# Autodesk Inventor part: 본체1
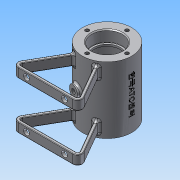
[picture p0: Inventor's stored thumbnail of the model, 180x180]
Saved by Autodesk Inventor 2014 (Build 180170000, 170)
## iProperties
Created: 2016-03
Part Number: 본체1
Material: 알루미늄 6061
Document SubType Name: Modeling
Designer: NET
Density: 2.71 g/cm^3
Appearance: 알루미늄 - 평지
Mass: 209.662 g
Surface Area: 328.168 cm^2
Volume: 77.3661 cm^3
Author: NET
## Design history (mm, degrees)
sketch "스케치1"
  geometry: C1 r 26 at (0, 0); 1 further point
  constraints: 1 centre point, 1 coincident
  dimensions: "d0" = 52 diameter of C1
extrude "돌출1" new body sketch "스케치1" stored distance "d1" = 70; taper "d2" = 0 deg
node "작업 평면2"
sketch "스케치2"
  geometry: 1 further point
sketch "스케치3"
  geometry: L1 (0, 0)-(0, -65); L2 (0, 0)-(58.644, 0); L3 (0, -65)-(-37.528, -65); L4 (-37.528, -65)-(37.528, -65); L5 (-32.332, -62)-(32.332, -62); L6 (11.547, -20)-(37.528, -65); L7 (-9.815, -23)-(-32.332, -62); L8 (32.332, -62)-(9.815, -23); L9 (-11.547, -20)-(-37.528, -65); L10 (-11.547, -20)-(11.547, -20); L11 (9.815, -23)-(-9.815, -23); C1 r 26 at (0, 0) reference; 2 further points
  constraints: 22 end point, 2 midpoint, 2 parallel, 1 horizontal, 1 point on line, 1 vertical
  dimensions: "d4" = 65 distance of L1.end L1.start; "d10" = 3 distance between parallel lines of L4 L5; "d13" = 3 distance between parallel lines of L11 L10; "d14" = 3 distance between parallel lines of L6 L8; "d15" = 3 distance between parallel lines of L9 L7; "d17" = 51.96152 distance of L6.start L4.end; "d18" = 60 deg angle of L8 L7; "d19" = 75.05553 distance of L3.end L4.end; "d112" = 45 distance between parallel lines of L4 L10
extrude "돌출2" join sketch "스케치3" distance "d20" = 10; taper "d21" = 0 deg
fillet "모깎기1" dims "d22" = 5
fillet "모깎기2" dims "d23" = 2
sketch "스케치4"
  geometry: C1 r 26 at (0, 0) reference; C2 r 16 at (0, 0)
  constraints: 1 centre point, 1 coincident
  dimensions: "d24" = 32 diameter of C2
extrude "돌출3" cut sketch "스케치4" distance "d25" = 12; taper "d26" = 0 deg
sketch "스케치5"
  geometry: C1 r 16 at (0, 0) reference; C2 r 14 at (0, 0)
  constraints: 1 centre point, 1 coincident
  dimensions: "d27" = 28 diameter of C2
extrude "돌출4" cut sketch "스케치5" distance "d28" = 2; taper "d29" = 0 deg
node "작업 평면4"
fillet "모깎기3" dims "d33" = 0.3
node "작업 평면5"
sketch "스케치7"
  geometry: C1 r 21 at (0, 0); 1 further point
  constraints: 1 centre point, 1 coincident
  dimensions: "d37" = 42 diameter of C1
extrude "돌출6" cut sketch "스케치7" stored distance "d38" = 42; taper "d39" = 0 deg
fillet "모깎기7" dims "d40" = 3
fillet "모깎기8" dims "d41" = 0.3
node "작업 평면6"
sketch "스케치8"
  geometry: C1 r 5 at (0, 0); 1 further point
  constraints: 1 centre point, 1 coincident
  dimensions: "d43" = 10 diameter of C1
extrude "돌출7" join sketch "스케치8" stored distance "d44" = 42; taper "d45" = 0 deg
sketch "스케치9"
  geometry: L1 (0, 0)-(7.506, -28.012); L2 (0, 0)-(0, -26); 2 further points
  constraints: 4 end point, 1 coincident, 1 vertical, 1 vertical alignment, 1 other
  dimensions: "d46" = 15 deg angle of L1 L2; "d47" = 29 distance of L1.start L1.end
node "작업 평면7"
sketch "스케치10"
  geometry: C1 r 6 at (0, 0); 1 further point
  constraints: 1 centre point, 1 coincident
  dimensions: "d48" = 12 diameter of C1
extrude "돌출8" join sketch "스케치10" stored distance "d49" = 42; taper "d50" = 0 deg
hole "구멍1" diameter "d53" = 5.188; stored, may be unused: countersink angle "d57" = 90 deg, drill point angle "d59" = 118 deg; dims "d51" = 10, "d52" = 10, "d54" = 10, "d55" = 4, "d56" = 2, "d58" = 10
hole "구멍2" diameter "d62" = 5.188; stored, may be unused: countersink angle "d66" = 90 deg, drill point angle "d68" = 118 deg; dims "d60" = 10, "d61" = 10, "d63" = 10, "d64" = 4, "d65" = 2, "d67" = 10
fillet "모깎기9" dims "d69" = 2
fillet "모깎기10" dims "d70" = 2
fillet "모깎기11" dims "d71" = 2
fillet "모깎기12" dims "d72" = 5
sketch "스케치11"
  geometry: L1 (0, 0)-(57.735, 0) reference; L2 (57.735, 10)-(0, 10) reference; L3 (28.868, 10)-(28.868, 0); C1 r 3 at (8.868, 5); C2 r 3 at (48.868, 5); 1 further point
  constraints: 2 centre point, 2 end point, 2 midpoint, 1 horizontal alignment
  dimensions: "d73" = 6 diameter of C1; "d74" = 6 diameter of C2; "d75" = 20 distance from line of C1.centre L3; "d76" = 40 distance of C2.centre C1.centre; "d77" = 5 distance from line of L1 C1.centre
extrude "돌출9" cut sketch "스케치11" distance "d78" = 42; taper "d79" = 0 deg
node "작업 평면8"
sketch "스케치12"
  geometry: L1 (26, 35)-(-26, 35) reference; 2 further points
  constraints: 1 coincident, 1 other
feature "엠보싱1" sketch "스케치12" dims "d20" = 10, "d21" = 0, "d82" = 0.5, "d83" = 0
chamfer "모따기1" distance "d84" = 1; stored, may be unused: second distance "d85" = 2, angle "d86" = 45 deg
chamfer "모따기2" distance "d87" = 1; stored, may be unused: second distance "d88" = 2, angle "d89" = 45 deg
sketch "스케치13" dims "d91" = 42
  geometry: L1 (0, 21)-(0, 0); C1 r 17 at (0, 0) reference; 1 further point
  constraints: 2 coincident, 2 end point, 1 vertical, 1 vertical alignment, 2 other
hole "구멍3" sketch "스케치13" at (0, 21) diameter "d92" = 4; stored, may be unused: countersink angle "d96" = 90 deg, drill point angle "d98" = 118 deg; dims "d93" = 6, "d94" = 4, "d95" = 2, "d97" = 10
feature "스레드1" dims "d99" = 8, "d100" = 0
feature "스레드2" dims "d104" = 8, "d105" = 0
fillet "모깎기13" dims "d109" = 0.5
fillet "모깎기14" dims "d110" = 0.5
fillet "모깎기15" dims "d111" = 3
node "솔리드1"
mirror "대칭4"
mirror "대칭5"
pattern_circular "원형 패턴1" dims angle "d102" = 360 deg
mirror "대칭6"
pattern_circular "원형 패턴2" dims "d107" = 360 deg
other parameters: "d6" = 30 deg, "d7" = 30 deg, "d8" = 3, "d9" = 3, "d11" = 3, "d12" = 45, "d42" = 29, "d80" = 26
